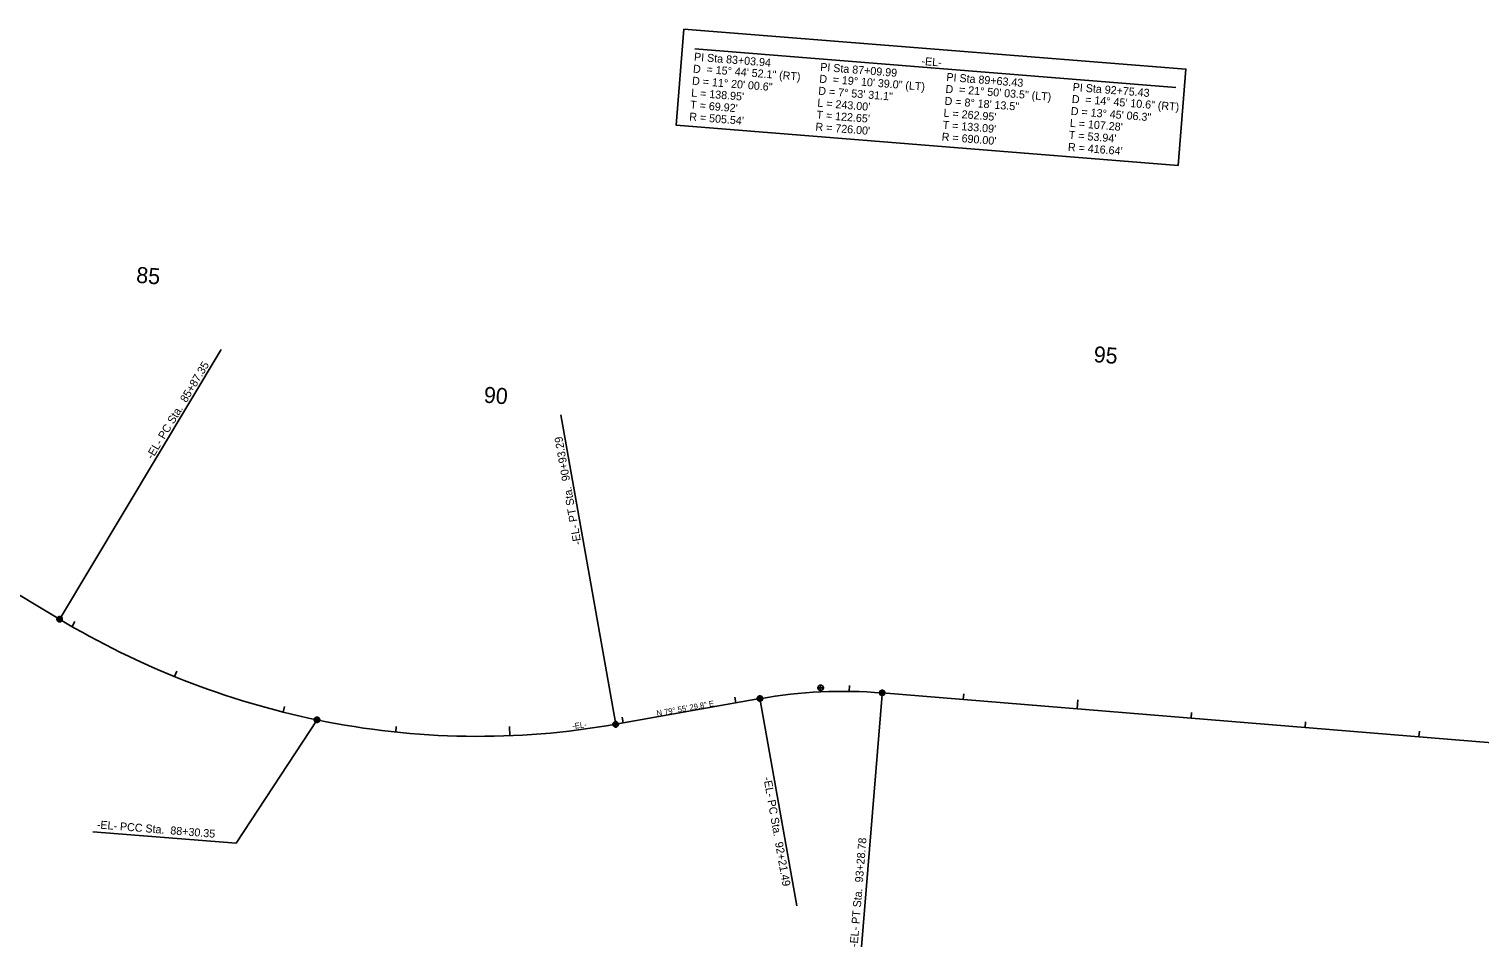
# Model space of a CAD drawing. Extents: x 928071 to 937324, y 684061 to 686812.
# Drawn here: x 934785 to 936055, y 684241 to 685045 of the extents above; entities that cross this region are included whole.
import ezdxf

# ---------------------------------------------------------------- set-up
doc = ezdxf.new("R2010")
doc.units = 0
for name, color, linetype in [('COGO Default Chain', 7, 'Continuous'), ('COGO Default Curve', 7, 'Continuous'), ('Cogo Default Point CELL', 7, 'Continuous'), ('Default', 7, 'Continuous'), ('Exist Horizontal Alignment', 7, 'Continuous'), ('Exist Horizontal Alignment Curve and Spiral Data', 7, 'Continuous'), ('Exist Horizontal Alignment Direction Label', 7, 'Continuous'), ('Exist Horizontal Alignment Station Label', 7, 'Continuous'), ('Exist Horizontal Alignment Tick Label', 7, 'Continuous'), ('Exist Horizontal Alignment Tick Large', 7, 'Continuous'), ('Exist Horizontal Alignment Tick Small', 7, 'Continuous'), ('Prop DSN Text', 7, 'Continuous')]:
    doc.layers.add(name, color=color, linetype=linetype)

msp = doc.modelspace()

# ---------------------------------------------------------------- linework, layer by layer
at = {"layer": 'COGO Default Chain'}
for p, q in [((934628.1, 684638.3), (934812, 684528.1)), ((935298.6, 684436.2), (935424.8, 684458.7)), ((935531.7, 684463.7), (936738.6, 684364.9))]:
    msp.add_line(p, q, dxfattribs=at)
for centre, radius, start, end in [((935185.2, 685150.8), 726, 239.0633, 258.2408), ((935497.7, 684048.4), 416.6, 85.3221, 100.0751), ((935177.9, 685115.6), 690, 258.2408, 280.0751)]:
    msp.add_arc(centre, radius, start, end, dxfattribs=at)
at = {"layer": 'COGO Default Curve'}
for centre, radius, start, end in [((935185.2, 685150.8), 726, 239.0633, 258.2408), ((935497.7, 684048.4), 416.6, 85.3221, 100.0751), ((935177.9, 685115.6), 690, 258.2408, 280.0751)]:
    msp.add_arc(centre, radius, start, end, dxfattribs=at)
at = {"layer": 'Cogo Default Point CELL'}
for points in [[(934809, 684528.1), (934812, 684528.1)], [(934812, 684531.1), (934812, 684528.1)], [(934812, 684528.1), (934815, 684528.1)], [(934812, 684528.1), (934812, 684525.1)], [(935477.9, 684471.1), (935477.9, 684468.1)], [(935421.8, 684458.7), (935424.8, 684458.7)], [(935424.8, 684461.7), (935424.8, 684458.7)], [(935424.8, 684458.7), (935427.8, 684458.7)], [(935424.8, 684458.7), (935424.8, 684455.7)], [(935474.9, 684468.1), (935477.9, 684468.1)], [(935477.9, 684468.1), (935480.9, 684468.1)], [(935477.9, 684468.1), (935477.9, 684465.1)], [(935528.7, 684463.7), (935531.7, 684463.7)], [(935531.7, 684466.7), (935531.7, 684463.7)], [(935531.7, 684463.7), (935534.7, 684463.7)], [(935531.7, 684463.7), (935531.7, 684460.7)], [(935034.3, 684440.1), (935037.3, 684440.1)], [(935034.3, 684440.1), (935037.3, 684440.1)], [(935037.3, 684443.1), (935037.3, 684440.1)], [(935037.3, 684443.1), (935037.3, 684440.1)], [(935037.3, 684440.1), (935040.3, 684440.1)], [(935037.3, 684440.1), (935037.3, 684437.1)], [(935037.3, 684440.1), (935040.3, 684440.1)], [(935037.3, 684440.1), (935037.3, 684437.1)], [(935295.6, 684436.2), (935298.6, 684436.2)], [(935298.6, 684439.2), (935298.6, 684436.2)], [(935298.6, 684436.2), (935301.6, 684436.2)], [(935298.6, 684436.2), (935298.6, 684433.2)]]:
    msp.add_lwpolyline(points, dxfattribs=at)
for centre in [(934812, 684528.1), (935477.9, 684468.1), (935424.8, 684458.7), (935531.7, 684463.7), (935037.3, 684440.1), (935037.3, 684440.1), (935298.6, 684436.2)]:
    msp.add_circle(centre, 2.34, dxfattribs=at)
at = {"layer": 'Default'}
for p, q in [((934812, 684528.1), (934628.1, 684638.3)), ((935298.6, 684436.2), (935424.8, 684458.7)), ((936738.6, 684364.9), (935531.7, 684463.7))]:
    msp.add_line(p, q, dxfattribs=at)
msp.add_lwpolyline([(935358.2, 685044.5), (935797.5, 685009.4), (935790.8, 684925.2), (935351.5, 684960.3)], close=True, dxfattribs=at)
for centre, radius, start, end in [((935185.2, 685150.8), 726, 239.0633, 258.2408), ((935497.7, 684048.4), 416.6, 85.3221, 100.0751), ((935177.9, 685115.6), 690, 258.2408, 280.0751)]:
    msp.add_arc(centre, radius, start, end, dxfattribs=at)
at = {"layer": 'Exist Horizontal Alignment'}
for p, q in [((934628.1, 684638.3), (934812, 684528.1)), ((935298.6, 684436.2), (935424.8, 684458.7)), ((935531.7, 684463.7), (936738.6, 684364.9))]:
    msp.add_line(p, q, dxfattribs=at)
for centre, radius, start, end in [((935185.2, 685150.8), 726, 239.0633, 258.2408), ((935497.7, 684048.4), 416.6, 85.3221, 100.0751), ((935177.9, 685115.6), 690, 258.2408, 280.0751)]:
    msp.add_arc(centre, radius, start, end, dxfattribs=at)
at = {"layer": 'Exist Horizontal Alignment Curve and Spiral Data'}
msp.add_line((935367.8, 685027.1), (935788.7, 684993.4), dxfattribs=at)
at = {"layer": 'Exist Horizontal Alignment Station Label'}
for p, q in [((934812.8, 684529.4), (934953.4, 684764)), ((935298.3, 684437.7), (935250.5, 684707)), ((935425.1, 684457.2), (935457, 684277.3)), ((935531.6, 684462.2), (935513.5, 684241.3)), ((934966.5, 684332.1), (935037.3, 684440.1)), ((934966.5, 684332.1), (934841.1, 684342.2))]:
    msp.add_line(p, q, dxfattribs=at)
for centre in [(934812, 684528.1), (935424.8, 684458.7), (935531.7, 684463.7), (935037.3, 684440.1), (935298.6, 684436.2)]:
    msp.add_circle(centre, 1.5, dxfattribs=at)
at = {"layer": 'Exist Horizontal Alignment Tick Large'}
for p, q in [((935702.3, 684449.7), (935703, 684457.7)), ((935205.9, 684426.2), (935205.6, 684434.2))]:
    msp.add_line(p, q, dxfattribs=at)
at = {"layer": 'Exist Horizontal Alignment Tick Small'}
for p, q in [((934822.9, 684521.7), (934825.4, 684526)), ((934912.7, 684477.9), (934914.6, 684482.6)), ((935502.9, 684465), (935503, 684470)), ((935403.7, 684454.9), (935402.8, 684459.8)), ((935602.7, 684457.9), (935603.1, 684462.9)), ((935007.7, 684446.9), (935008.9, 684451.7)), ((935802, 684441.6), (935802.4, 684446.6)), ((935106.1, 684429.3), (935106.6, 684434.3)), ((935305.2, 684437.4), (935304.3, 684442.3)), ((935901.7, 684433.4), (935902.1, 684438.4)), ((936001.3, 684425.3), (936001.7, 684430.2))]:
    msp.add_line(p, q, dxfattribs=at)

# ---------------------------------------------------------------- texts
at = {"layer": 'Exist Horizontal Alignment Curve and Spiral Data'}
for s, p in [('PI Sta 83+03.94', (935366.9, 685016.9)), ('-EL-', (935565.9, 685013.1)), ('D = 11%%d 20\' 00.6"', (935365.2, 684995.9)), ('D', (935366, 685006.4)), ('= 15%%d 44\' 52.1" (RT)', (935377.8, 685005.9)), ('D', (935476.5, 684997.6)), ('PI Sta 87+09.99', (935477.3, 685008)), ('= 19%%d 10\' 39.0" (LT)', (935488.2, 684997)), ('PI Sta 89+63.43', (935587.7, 684999.2)), ("L = 138.95'", (935364.4, 684985.5)), ('D = 7%%d 53\' 31.1"', (935475.6, 684987.1)), ('D', (935586.9, 684988.7)), ('= 21%%d 50\' 03.5" (LT)', (935598.7, 684988.2)), ('PI Sta 92+75.43', (935698.2, 684990.4)), ("T = 69.92'", (935363.5, 684975)), ("L = 243.00'", (935474.8, 684976.6)), ('D = 8%%d 18\' 13.5"', (935586.1, 684978.3)), ('D', (935697.4, 684979.9)), ('= 14%%d 45\' 10.6" (RT)', (935709.1, 684979.4)), ("R = 505.54'", (935362.7, 684964.5)), ("T = 122.65'", (935474, 684966.2)), ("T = 133.09'", (935584.4, 684957.3)), ("L = 262.95'", (935585.2, 684967.8)), ("L = 107.28'", (935695.7, 684959)), ('D = 13%%d 45\' 06.3"', (935696.5, 684969.4)), ("R = 726.00'", (935473.1, 684955.7)), ("R = 690.00'", (935583.6, 684946.9)), ("T = 53.94'", (935694.8, 684948.5)), ("R = 416.64'", (935694, 684938))]:
    msp.add_text(s, height=7, rotation=355.4267, dxfattribs=at).set_placement(p)
at = {"layer": 'Exist Horizontal Alignment Direction Label'}
msp.add_text('N 79%%d 55\' 29.8" E', height=5, rotation=10.0751, dxfattribs=at).set_placement((935334.8, 684443.2))
at = {"layer": 'Exist Horizontal Alignment Station Label'}
for s, rotation, p in [('-EL- PC Sta.  85+87.35', 59.0633, (934893.3, 684667.6)), ('-EL- PT Sta.  90+93.29', 100.0751, (935268.6, 684593.8)), ('-EL- PC Sta.  92+21.49', 280.0751, (935427.8, 684389.5)), ('-EL- PCC Sta.  88+30.35', 355.4267, (934844.4, 684345.1)), ('-EL- PT Sta.  93+28.78', 85.3221, (935510.2, 684241))]:
    msp.add_text(s, height=7, rotation=rotation, dxfattribs=at).set_placement(p)
at = {"layer": 'Exist Horizontal Alignment Tick Label'}
for s, p in [('85', (934878.7, 684822.6)), ('95', (935716.4, 684753.1)), ('90', (935182.8, 684717.7))]:
    msp.add_text(s, height=14, rotation=355.4267, dxfattribs=at).set_placement(p)
at = {"layer": 'Prop DSN Text'}
msp.add_text('-EL-', height=5, rotation=7.7686, dxfattribs=at).set_placement((935260.9, 684432))

doc.saveas('drawing.dxf')
